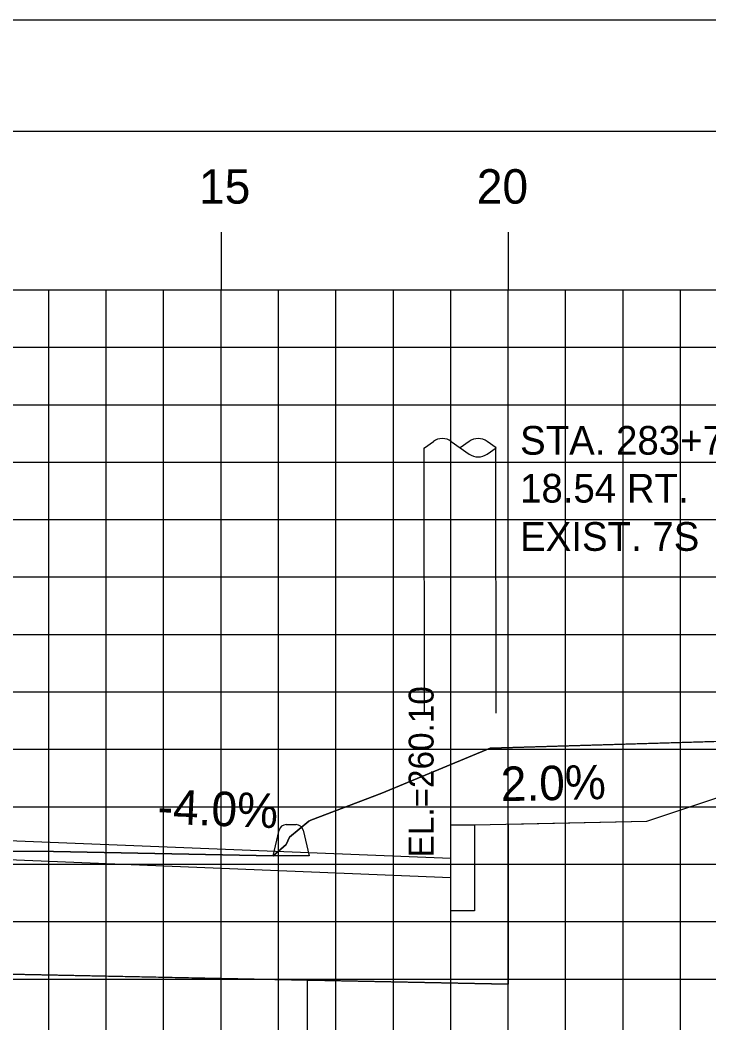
# Model space of a CAD drawing. Extents: x 856235 to 856405, y 366268 to 366378.
# Drawn here: x 856329.28 to 856341.28, y 366360.72 to 366378.18 of the extents above; entities that cross this region are included whole.
import ezdxf

# ---------------------------------------------------------------- set-up
doc = ezdxf.new("R2010")
doc.units = 0
for name, color, linetype in [('ANNOTATION', 7, 'Continuous'), ('BORDER', 7, 'Continuous'), ('D_Curb_Type_1_Rt', 7, 'Continuous'), ('D_Roadway_Edge_Shoulder', 7, 'Continuous'), ('D_Roadway_FinishedGrade', 7, 'Continuous'), ('D_Roadway_SubGrade', 7, 'Continuous'), ('D_Text_Monospaced', 7, 'Continuous'), ('D_Text_Standard', 7, 'Continuous'), ('H_V ANNOTATION', 7, 'Continuous'), ('JUNK COM EXC', 7, 'Continuous'), ('junk strct exc', 7, 'Continuous'), ('MAJOR', 7, 'Continuous'), ('MINOR', 7, 'Continuous'), ('PDRAIN', 7, 'Continuous'), ('PLOT BOUNDARY', 7, 'Continuous'), ('S_Curb_Type_3', 7, 'Continuous'), ('S_Roadway_Centerline', 7, 'Continuous'), ('S_Utilities_Pole_Power', 7, 'Continuous')]:
    doc.layers.add(name, color=color, linetype=linetype)

msp = doc.modelspace()

# ---------------------------------------------------------------- linework, layer by layer
at = {"layer": 'BORDER'}
msp.add_line((856402.781, 366376.236), (856242.781, 366376.236), dxfattribs=at)
at = {"layer": 'D_Curb_Type_1_Rt'}
msp.add_lwpolyline([(856337.197, 366364.167), (856337.197, 366362.667), (856336.78, 366362.667), (856336.78, 366364.167)], close=True, dxfattribs=at)
at = {"layer": 'D_Roadway_Edge_Shoulder'}
msp.add_lwpolyline([(856301.981, 366363.712), (856306.781, 366363.904), (856317.781, 366364.124), (856328.781, 366363.904), (856336.78, 366363.585)], dxfattribs=at)
at = {"layer": 'D_Roadway_FinishedGrade'}
for points in [[(856340.197, 366364.228), (856343.261, 366365.249)], [(856337.197, 366364.168), (856340.197, 366364.228)]]:
    msp.add_lwpolyline(points, dxfattribs=at)
at = {"layer": 'D_Roadway_SubGrade'}
for points in [[(856337.781, 366364.18), (856337.781, 366361.391), (856336.781, 366361.411)], [(856336.781, 366361.411), (856328.781, 366361.571), (856328.781, 366363.571), (856336.781, 366363.251)]]:
    msp.add_lwpolyline(points, dxfattribs=at)
at = {"layer": 'JUNK COM EXC'}
for points in [[(856346.125, 366365.758), (856337.467, 366365.5), (856335.581, 366364.715), (856334.342, 366364.246), (856334.308, 366364.232), (856333.97, 366363.951), (856333.914, 366363.825), (856333.689, 366363.627), (856329.863, 366363.704), (856328.954, 366363.708), (856326.986, 366363.743), (856318.175, 366364.117), (856309.225, 366363.802), (856307.438, 366363.733), (856301.74, 366363.432), (856300.981, 366363.404)], [(856300.981, 366363.404), (856300.702, 366363.394), (856300.563, 366363.43), (856296.348, 366363.536), (856294.317, 366363.378), (856292.601, 366363.365), (856286.23, 366363.117), (856265.781, 366362.934), (856265.781, 366361.768), (856290.981, 366362.395), (856300.981, 366361.439), (856306.781, 366361.571), (856317.781, 366361.791), (856328.781, 366361.571), (856337.781, 366361.391), (856337.781, 366364.18), (856340.197, 366364.228), (856343.261, 366365.249)]]:
    msp.add_lwpolyline(points, dxfattribs=at)
at = {"layer": 'junk strct exc'}
msp.add_lwpolyline([(856334.281, 366361.461), (856334.281, 366357.531), (856337.781, 366357.531), (856337.781, 366361.391)], close=True, dxfattribs=at)
at = {"layer": 'MAJOR'}
for p, q in [((856332.781, 366374.483), (856332.781, 366373.481)), ((856337.781, 366374.483), (856337.781, 366373.481)), ((856247.781, 366373.481), (856387.781, 366373.481)), ((856247.781, 366373.481), (856387.781, 366373.481)), ((856332.781, 366353.481), (856332.781, 366373.481)), ((856337.781, 366353.481), (856337.781, 366373.481)), ((856247.781, 366368.481), (856387.781, 366368.481)), ((856247.781, 366363.481), (856387.781, 366363.481))]:
    msp.add_line(p, q, dxfattribs=at)
at = {"layer": 'MINOR'}
for p, q in [((856329.781, 366353.481), (856329.781, 366373.481)), ((856330.781, 366353.481), (856330.781, 366373.481)), ((856331.781, 366353.481), (856331.781, 366373.481)), ((856333.781, 366353.481), (856333.781, 366373.481)), ((856334.781, 366353.481), (856334.781, 366373.481)), ((856335.781, 366353.481), (856335.781, 366373.481)), ((856336.781, 366353.481), (856336.781, 366373.481)), ((856338.781, 366353.481), (856338.781, 366373.481)), ((856339.781, 366353.481), (856339.781, 366373.481)), ((856340.781, 366353.481), (856340.781, 366373.481)), ((856247.781, 366372.481), (856387.781, 366372.481)), ((856247.781, 366371.481), (856387.781, 366371.481)), ((856247.781, 366370.481), (856387.781, 366370.481)), ((856247.781, 366369.481), (856387.781, 366369.481)), ((856247.781, 366367.481), (856387.781, 366367.481)), ((856247.781, 366366.481), (856387.781, 366366.481)), ((856247.781, 366365.481), (856387.781, 366365.481)), ((856247.781, 366364.481), (856387.781, 366364.481)), ((856247.781, 366362.481), (856387.781, 366362.481)), ((856247.781, 366361.481), (856387.781, 366361.481))]:
    msp.add_line(p, q, dxfattribs=at)
at = {"layer": 'PDRAIN'}
msp.add_lwpolyline([(856334.281, 366361.461), (856334.281, 366357.531), (856337.781, 366357.531), (856337.781, 366361.391)], dxfattribs=at)
at = {"layer": 'PLOT BOUNDARY'}
msp.add_lwpolyline([(856234.688, 366268.177), (856404.688, 366268.177), (856404.688, 366378.177), (856234.688, 366378.177)], close=True, dxfattribs=at)
at = {"layer": 'S_Curb_Type_3'}
for points in [[(856333.913, 366364.169), (856334.089, 366364.169)], [(856334.211, 366364.072), (856334.314, 366363.627), (856333.689, 366363.627), (856333.791, 366364.072)]]:
    msp.add_lwpolyline(points, dxfattribs=at)
for centre, start, end in [((856333.913, 366364.044), 90, 167.0054), ((856334.089, 366364.044), 12.9946, 90)]:
    msp.add_arc(centre, 0.125, start, end, dxfattribs=at)
at = {"layer": 'S_Roadway_Centerline'}
msp.add_lwpolyline([(856328.954, 366363.708), (856329.863, 366363.704), (856333.689, 366363.627), (856333.914, 366363.825), (856333.97, 366363.951), (856334.308, 366364.232), (856334.342, 366364.246), (856335.581, 366364.715), (856337.467, 366365.5), (856349.355, 366365.853), (856352.52, 366365.887), (856356.926, 366365.979), (856360.623, 366365.787), (856360.773, 366366.162), (856360.989, 366367.526), (856361.112, 366367.411), (856361.186, 366367.157)], dxfattribs=at)
at = {"layer": 'S_Utilities_Pole_Power'}
for p, q in [((856336.321, 366366.112), (856336.318, 366370.732)), ((856336.321, 366370.732), (856336.478, 366370.842)), ((856336.79, 366370.842), (856336.946, 366370.732)), ((856337.103, 366370.842), (856336.946, 366370.732)), ((856336.946, 366370.732), (856337.103, 366370.621)), ((856337.571, 366370.732), (856337.415, 366370.842)), ((856337.415, 366370.621), (856337.571, 366370.732)), ((856337.571, 366366.112), (856337.568, 366370.732))]:
    msp.add_line(p, q, dxfattribs=at)
for centre, start, end in [((856336.634, 366370.621), 90, 125.2644), ((856336.634, 366370.621), 54.7356, 90), ((856337.259, 366370.621), 90, 125.2644), ((856337.259, 366370.621), 54.7356, 90), ((856337.259, 366370.842), 234.7356, 270), ((856337.259, 366370.842), 270, 305.2644)]:
    msp.add_arc(centre, 0.271, start, end, dxfattribs=at)

# ---------------------------------------------------------------- texts
at = {"layer": 'ANNOTATION'}
for s, rotation, p in [('2.0%', 1.146, (856337.658, 366364.577)), ('-4.0%', 357.7094, (856331.668, 366364.189))]:
    msp.add_text(s, height=0.6, rotation=rotation, dxfattribs=at).set_placement(p)
at = {"layer": 'D_Text_Monospaced'}
for s, height, p in [('STA. 283+78.68', 0.49998, (856337.988, 366370.61)), ('18.54 RT.', 0.5, (856337.988, 366369.776)), ('EXIST. 7S', 0.5, (856337.988, 366368.936))]:
    msp.add_text(s, height=height, dxfattribs=at).set_placement(p)
at = {"layer": 'D_Text_Standard'}
msp.add_text(' EL.=260.10', height=0.4335, rotation=90, dxfattribs=at).set_placement((856336.482, 366363.437))
at = {"layer": 'H_V ANNOTATION'}
for s, p in [('15', (856332.398, 366374.981)), ('20', (856337.235, 366374.981))]:
    msp.add_text(s, height=0.6, dxfattribs=at).set_placement(p)

doc.saveas('drawing.dxf')
